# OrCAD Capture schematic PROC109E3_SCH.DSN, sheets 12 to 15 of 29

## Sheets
12 12. SOC2: size C; title: SOC2
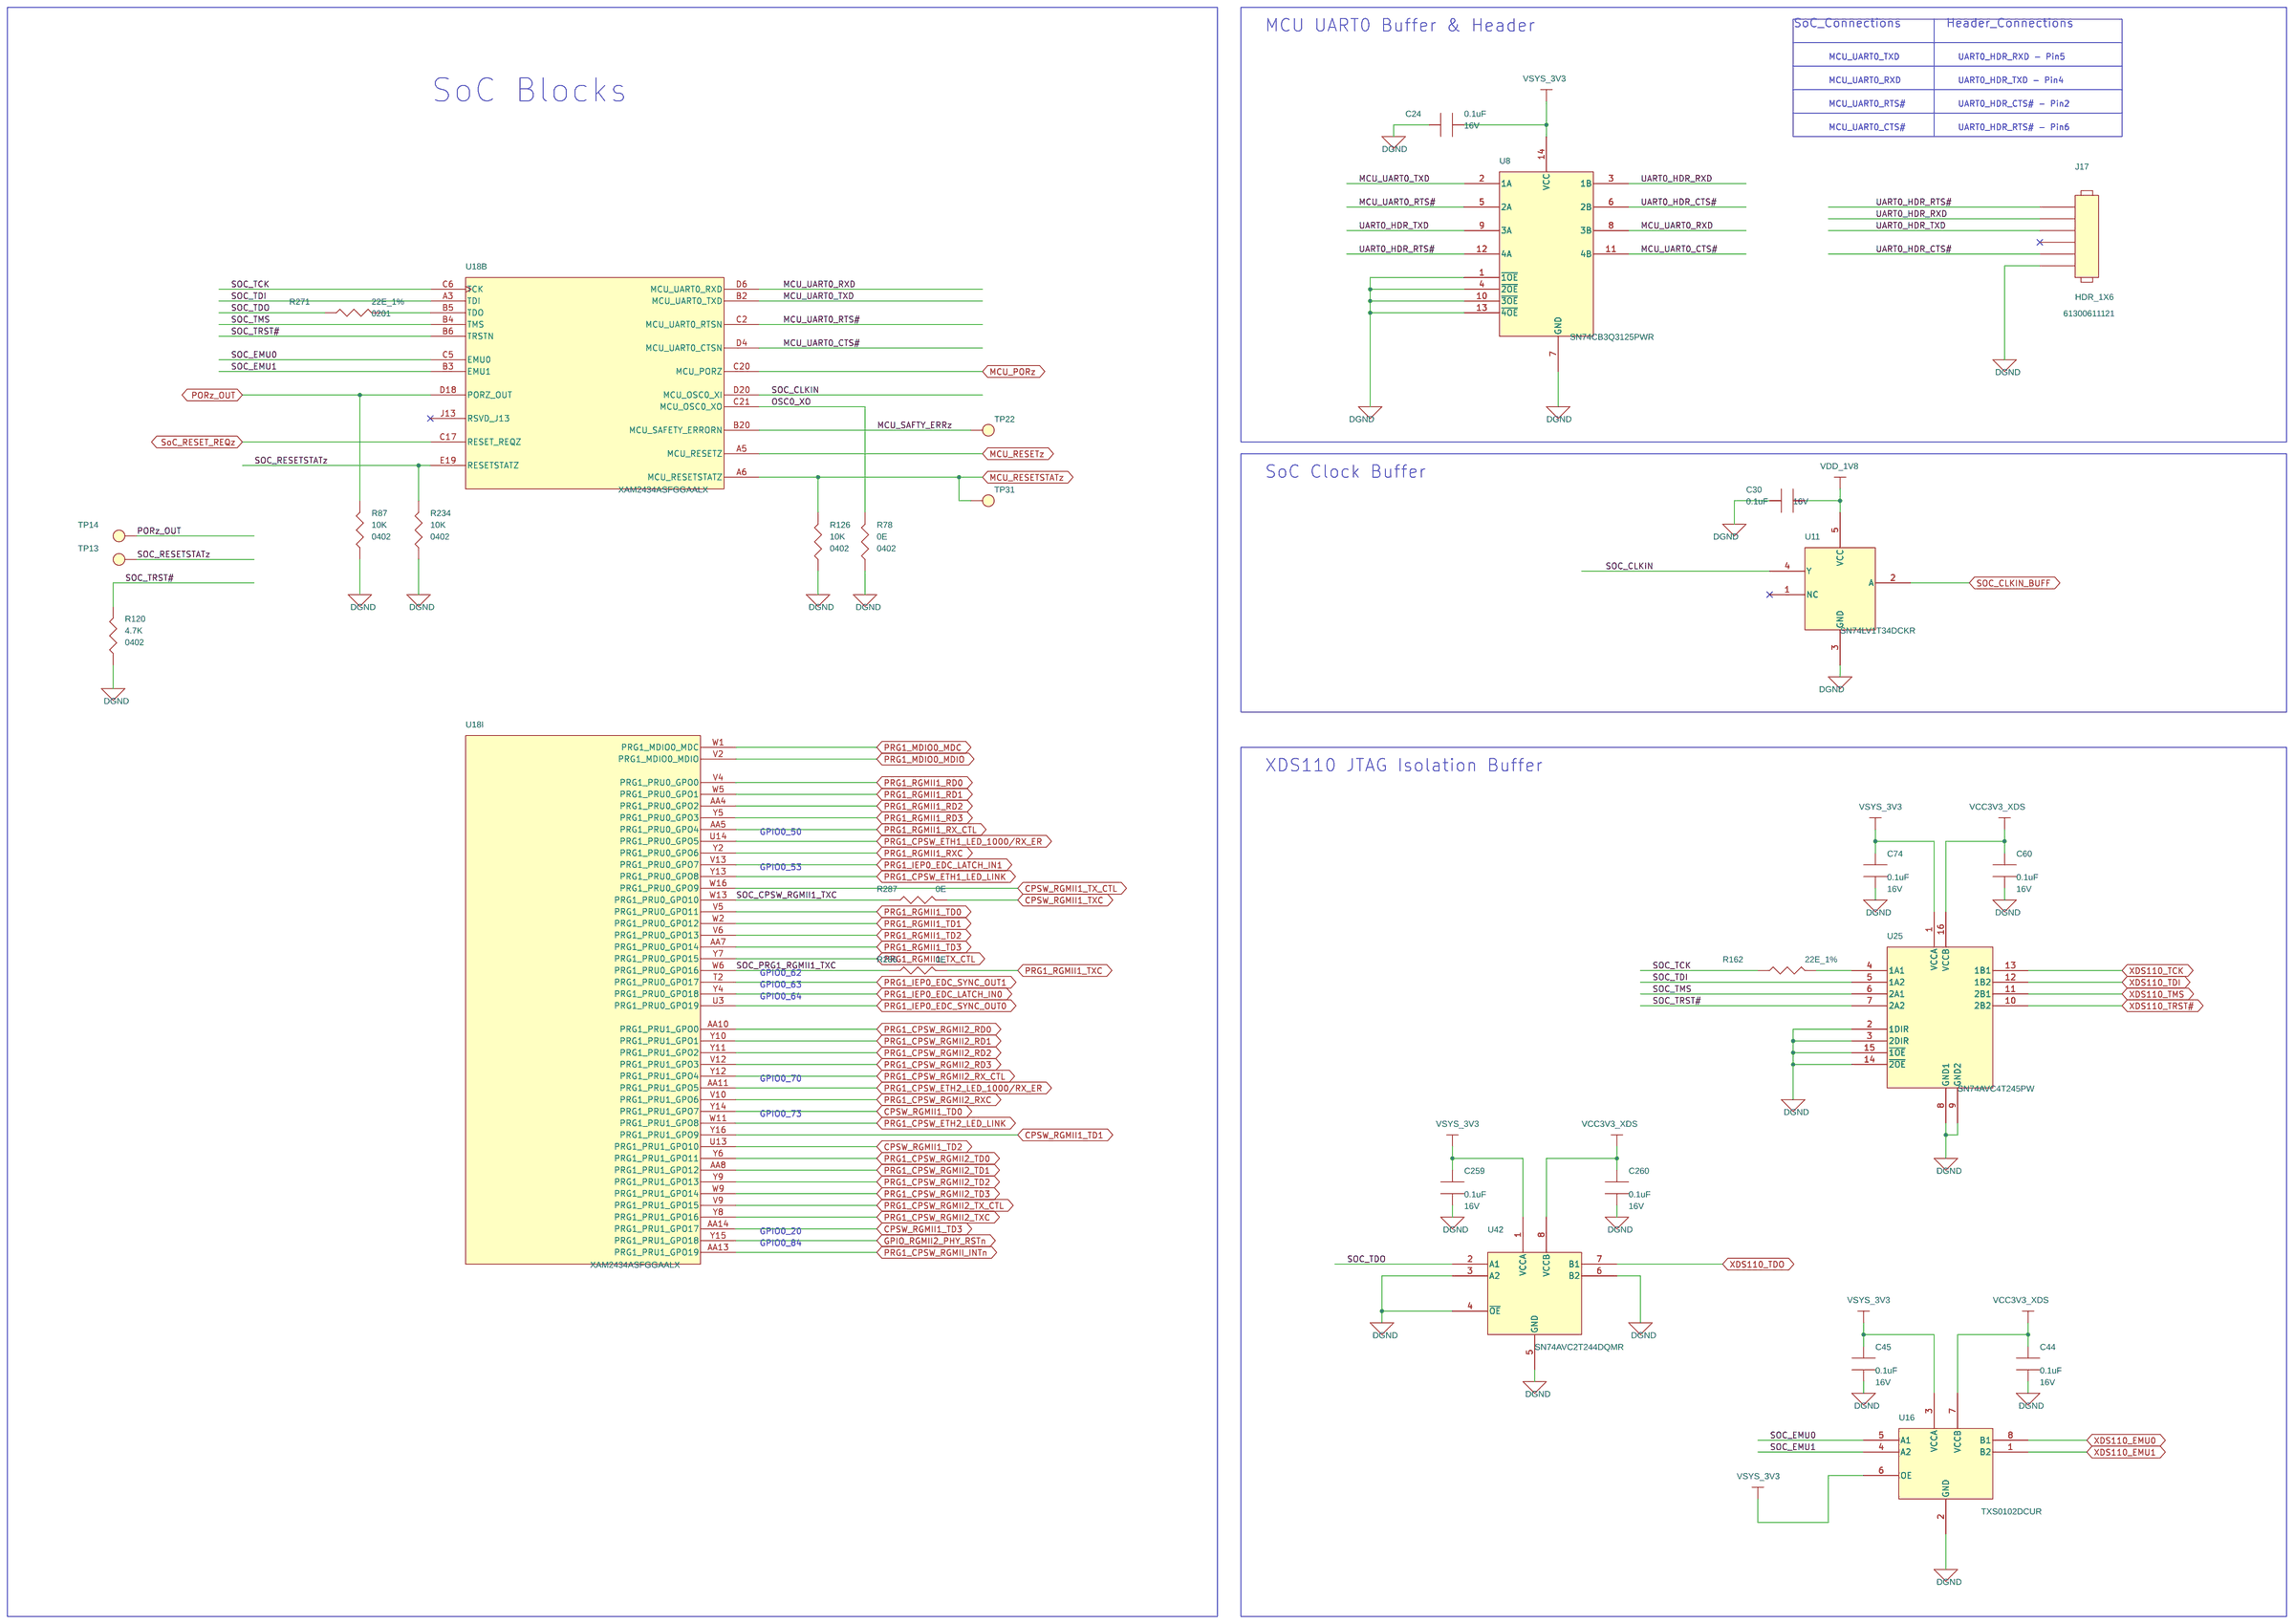
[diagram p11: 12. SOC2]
13 13. MCAN_eQEP_FSI_MUX_USR_LEDs: size C; title: MCAN_eQEP_FSI_MUX
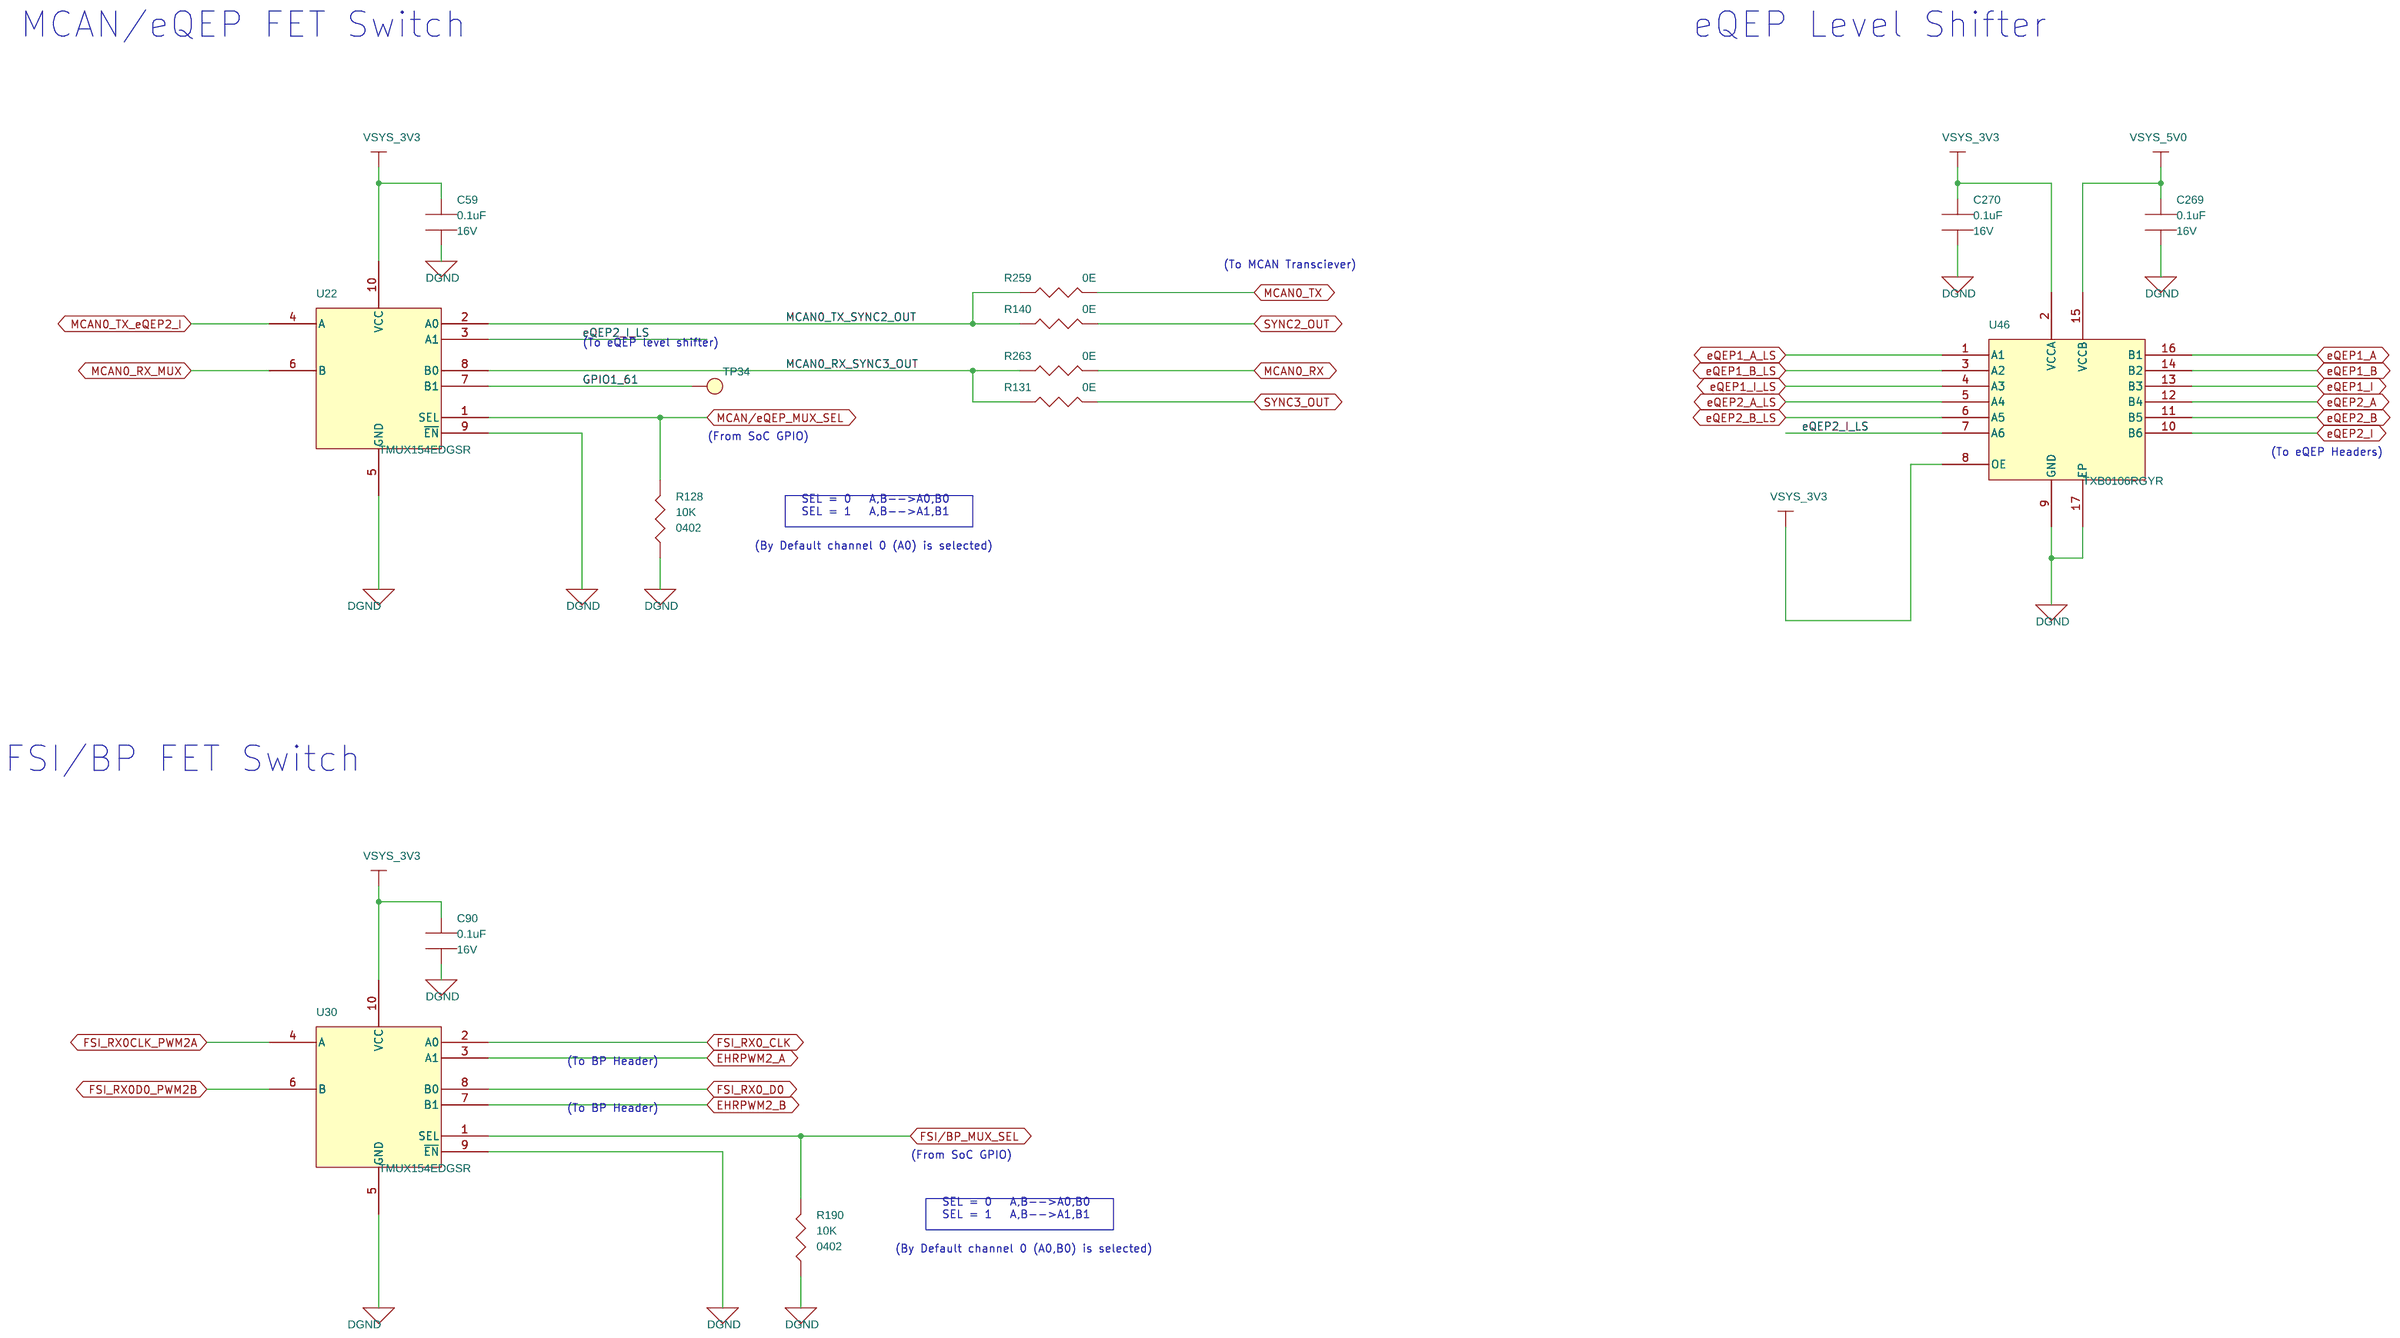
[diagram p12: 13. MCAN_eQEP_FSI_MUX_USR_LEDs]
14 14. CAN_eQEP_FSI_HDR_CLK_BUFFER: size C; title: CAN_eQEP_FSI_HEADERs & CLOCK BUFFER
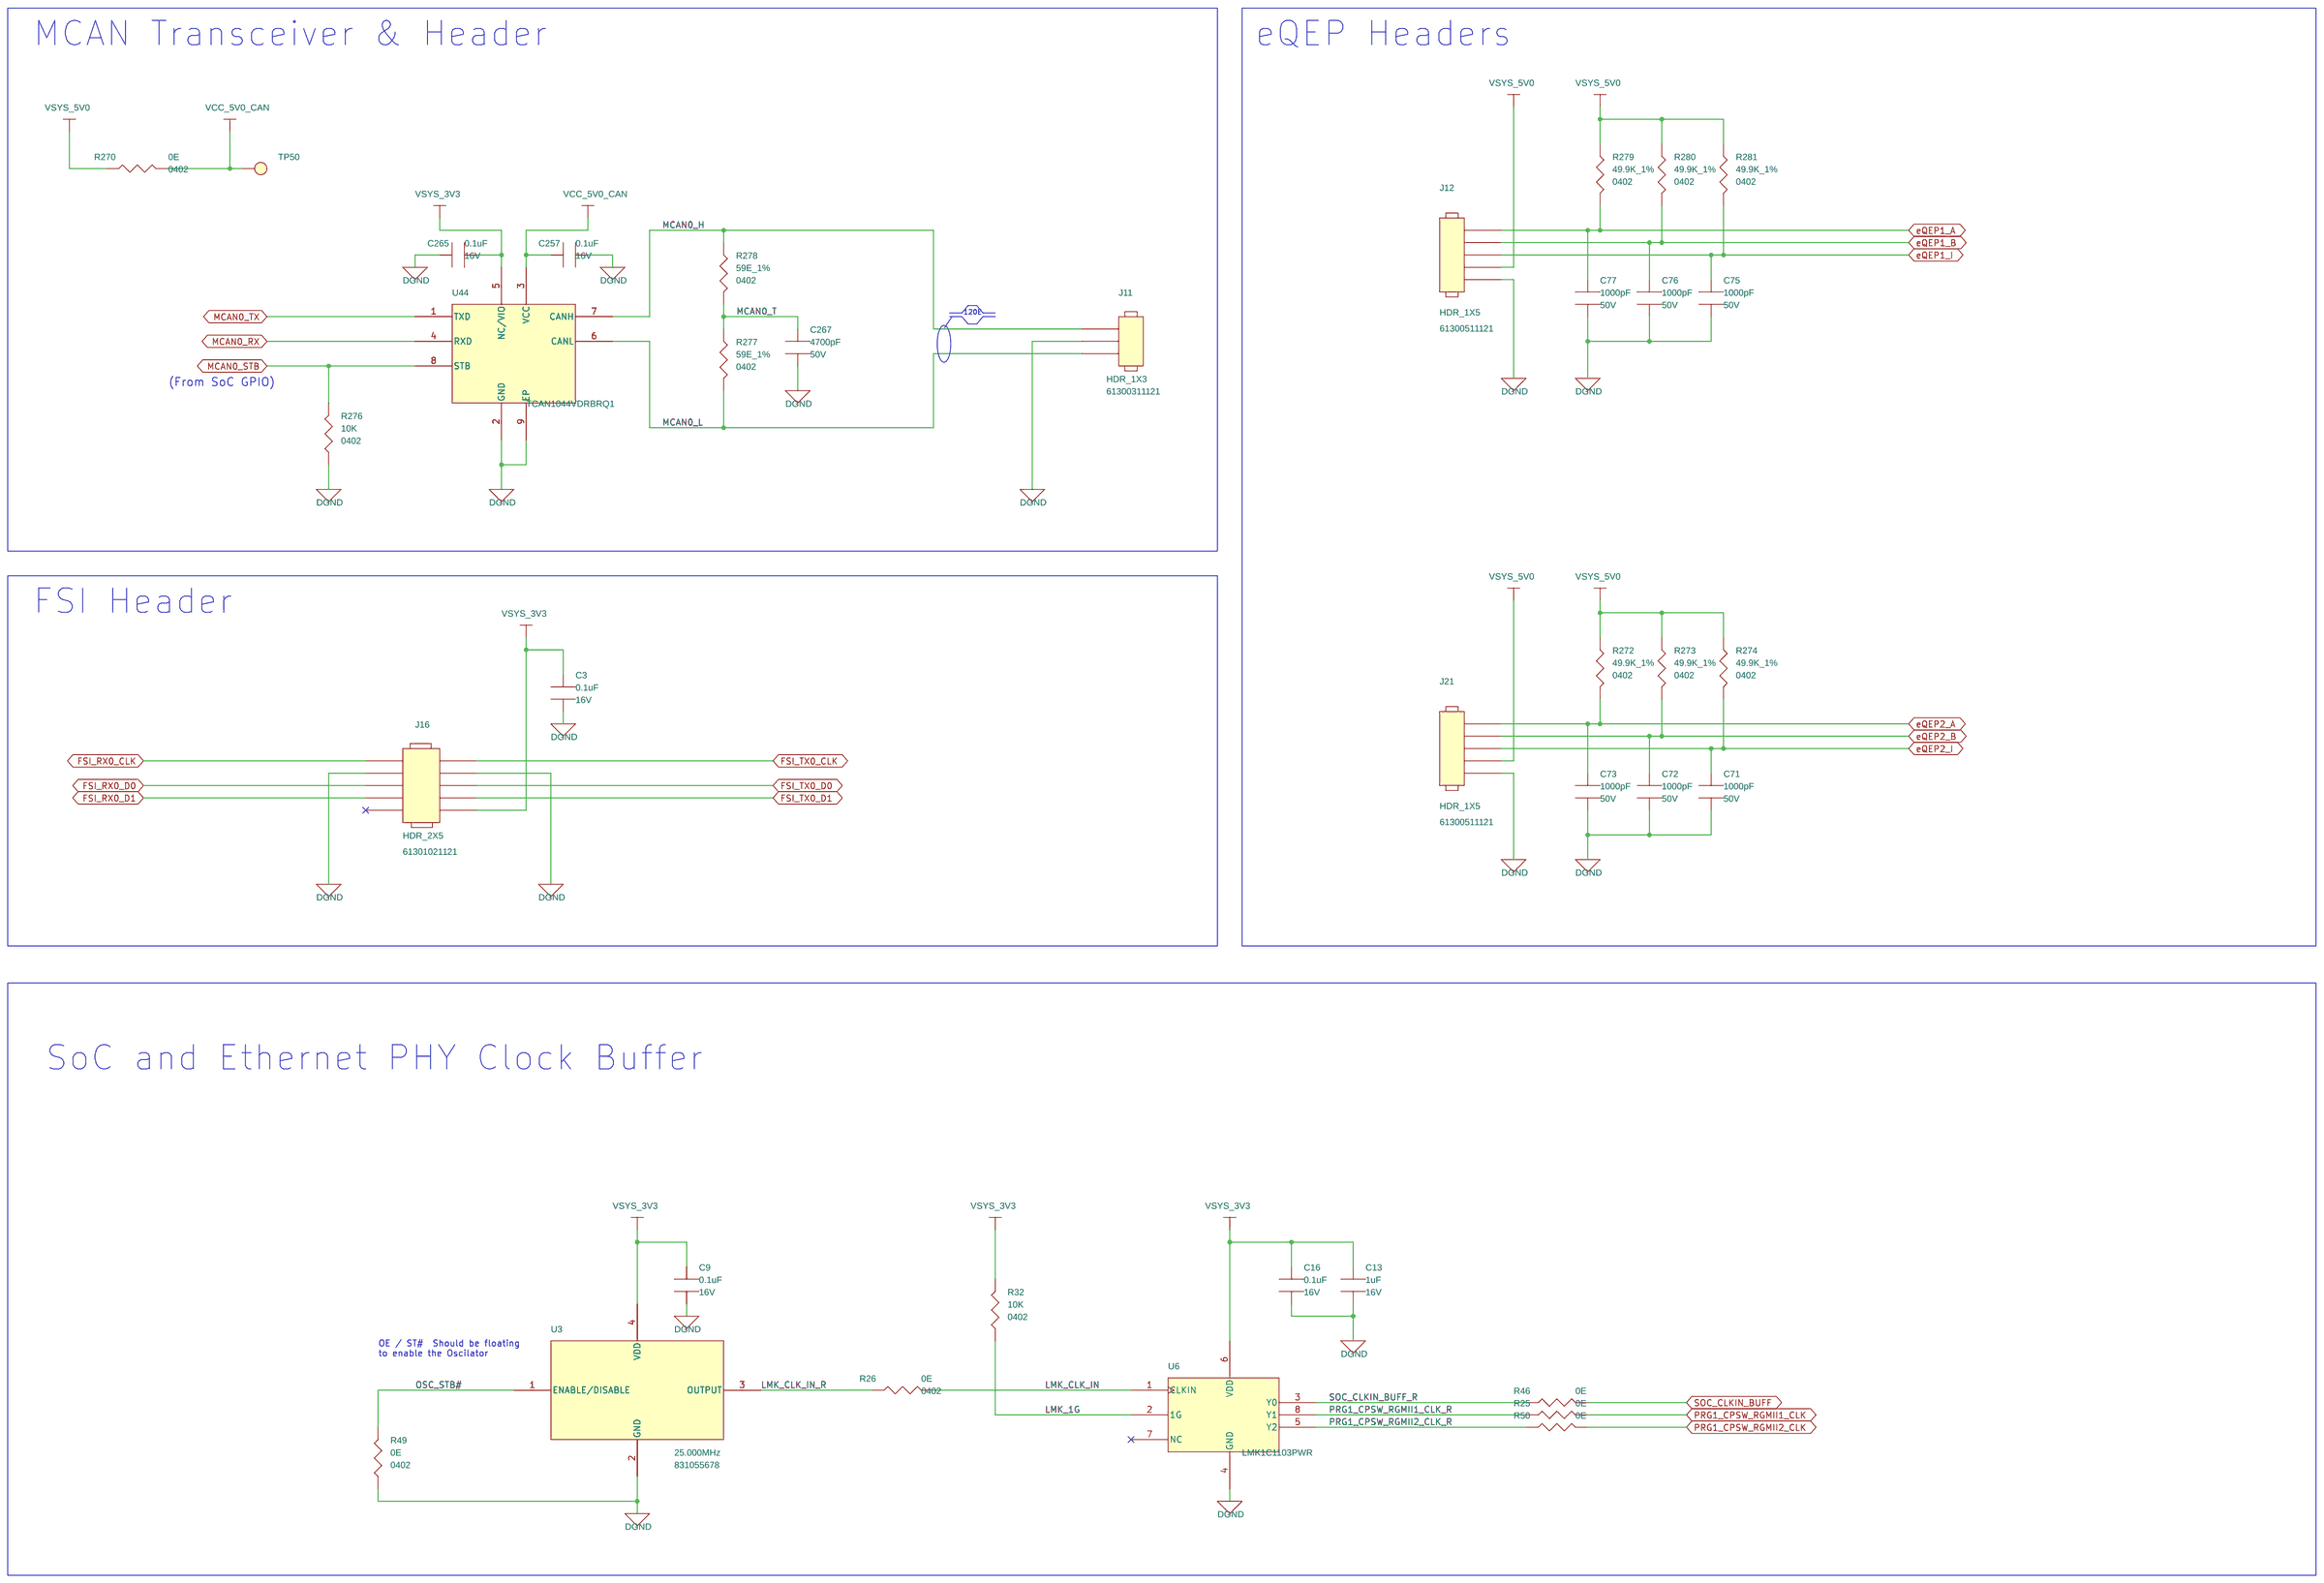
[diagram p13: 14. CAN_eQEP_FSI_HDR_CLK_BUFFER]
15 15. SOC_QSPI_BOARD_ID_EEPROM: size C; title: QSPI_BOARD_ID_EEPROM
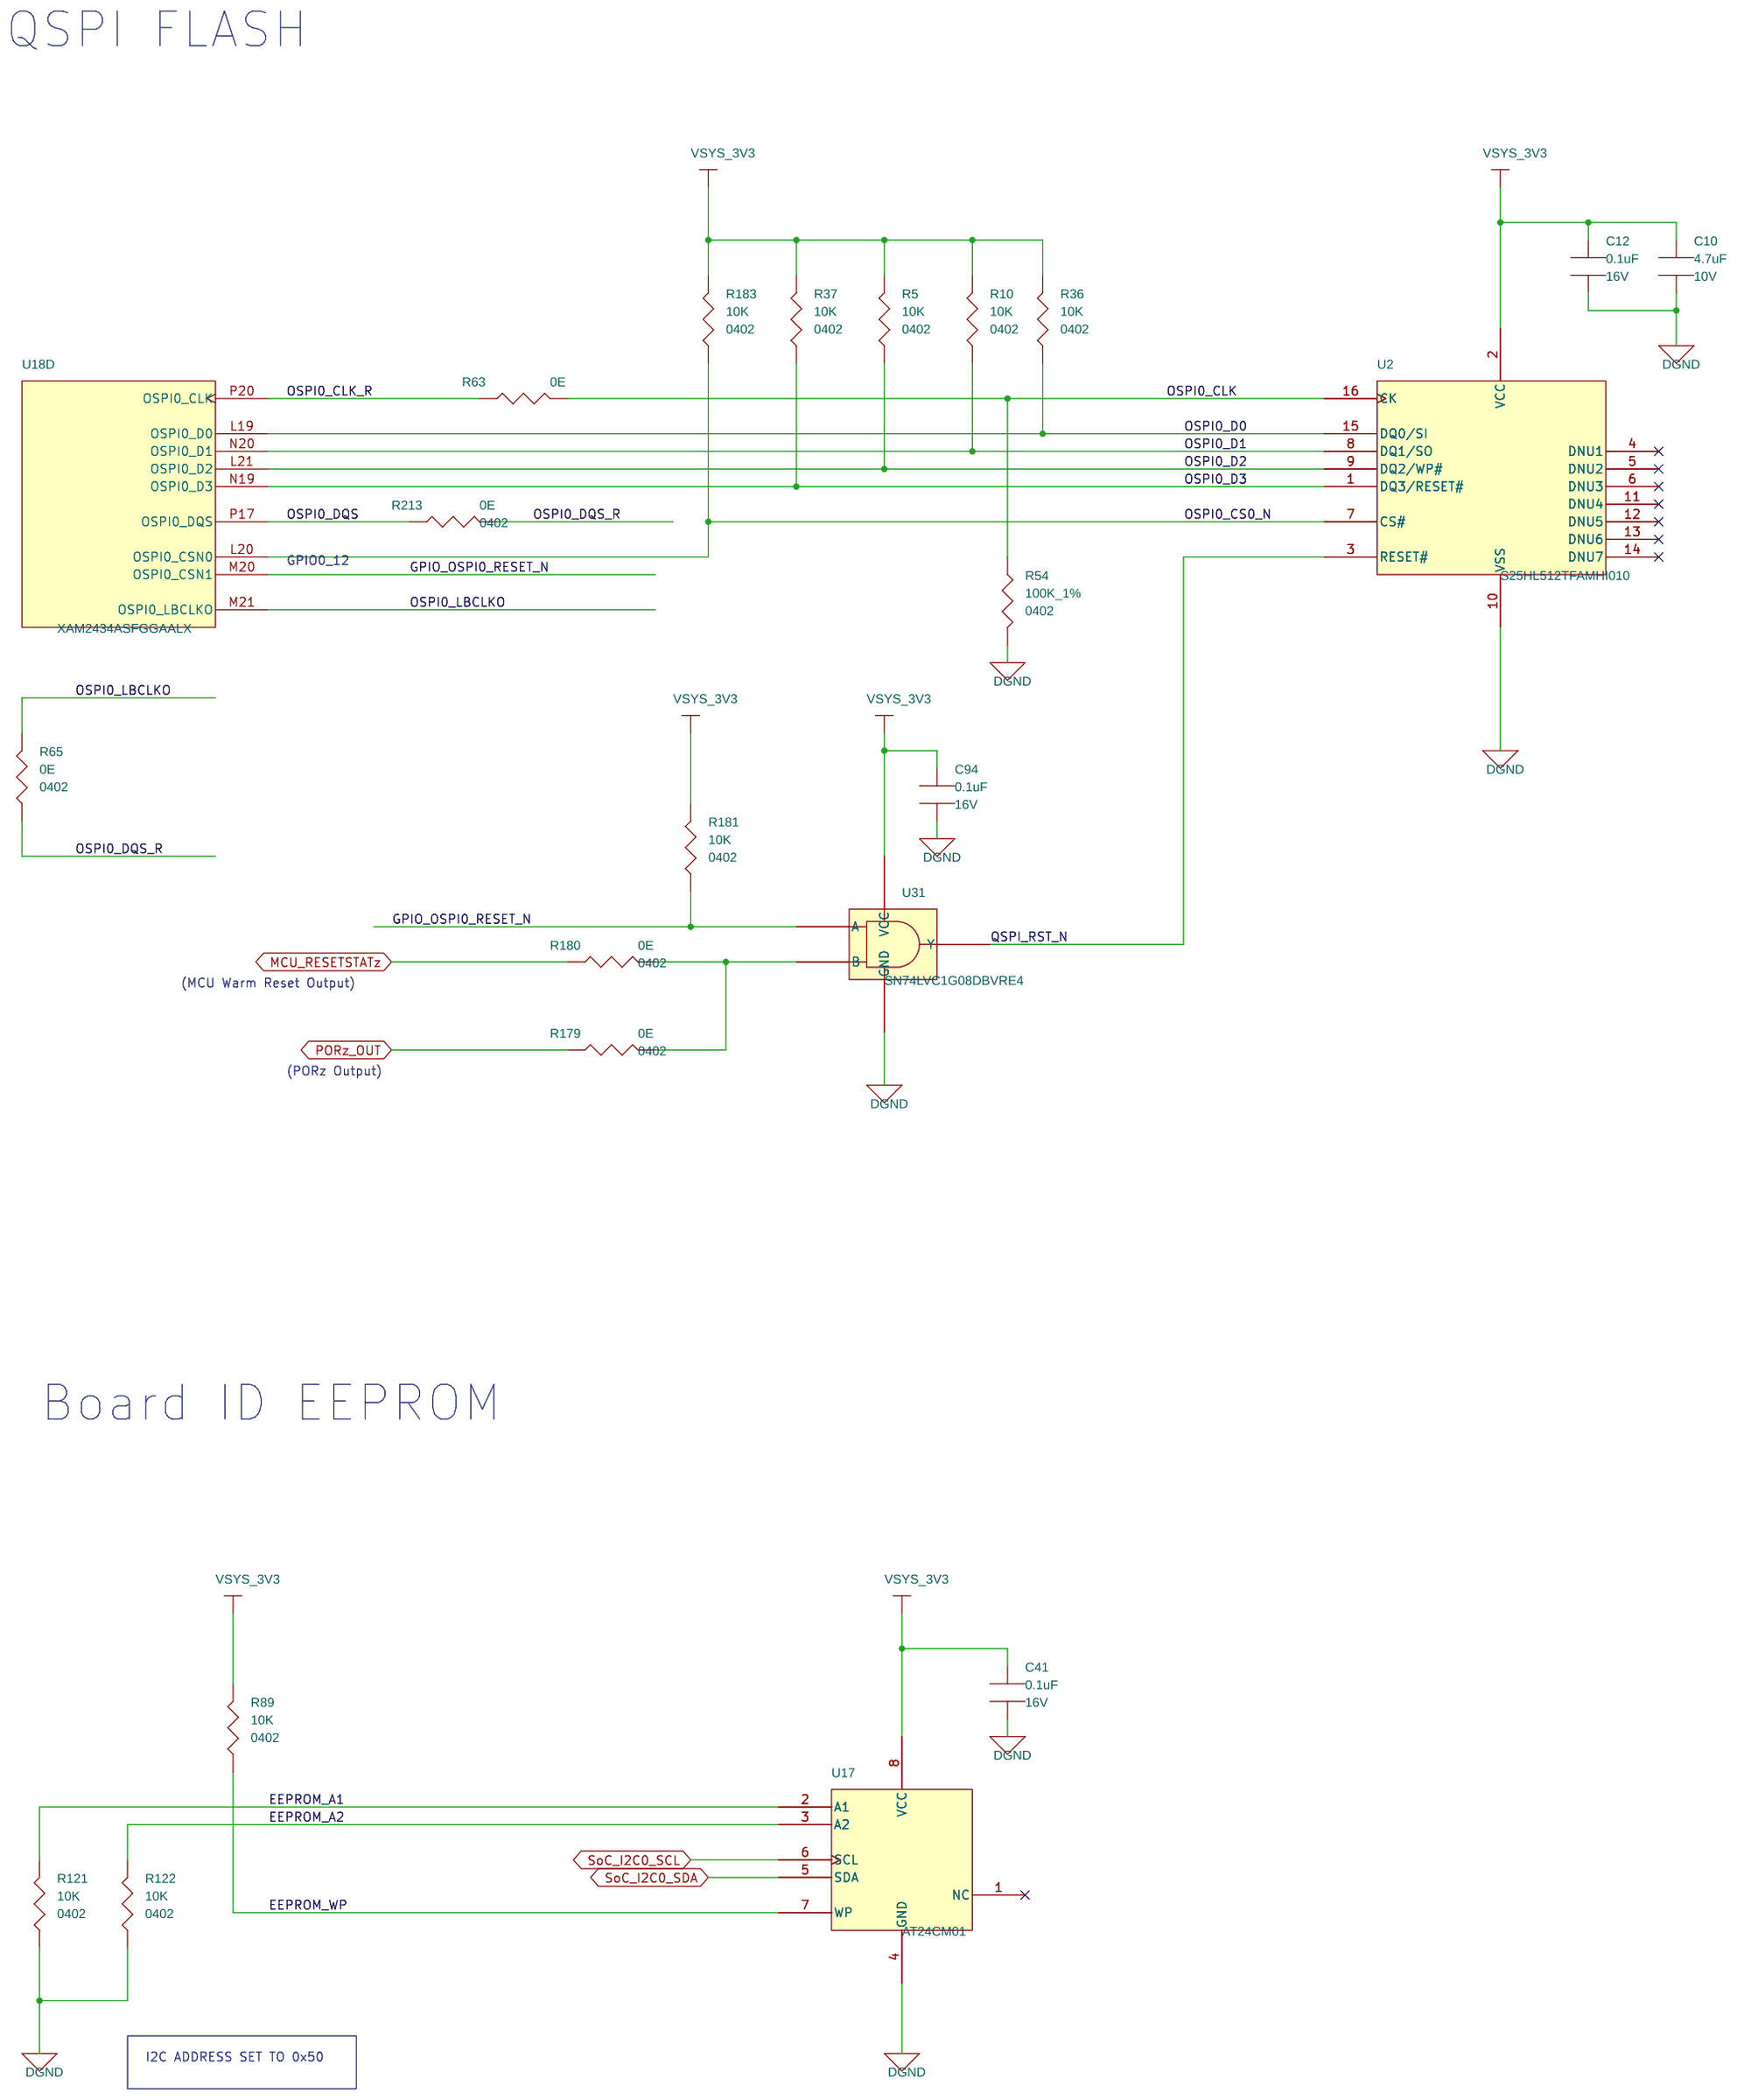
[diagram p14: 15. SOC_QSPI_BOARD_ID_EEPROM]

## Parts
sheet 12. SOC2
C24  0.1uF  [CAP0201_0-5]
C30  0.1uF  [CAP0201_0-5]
C44  0.1uF  [CAP0201_0-5]
C45  0.1uF  [CAP0201_0-5]
C60  0.1uF  [CAP0201_0-5]
C74  0.1uF  [CAP0201_0-5]
C259  0.1uF  [CAP0201_0-5]
C260  0.1uF  [CAP0201_0-5]
J17  HDR_1X6  [HDR_1X6_61300611121_S_T_8-6]
R78  0E  [RES0402_0-5]
R87  10K  [RES0402_0-5]
R120  4.7K  [RES0402_0-5]
R126  10K  [RES0402_0-5]
R162  22E_1%  [RES0201_0-5]
R234  10K  [RES0402_0-5]
R271  22E_1%  [RES0201_0-5]
R286  0E  [RES0402_0-5]
R287  0E  [RES0402_0-5]
TP13  TP20_SMD  [TP20_SMD]
TP14  TP20_SMD  [TP20_SMD]
TP22  TP20_SMD  [TP20_SMD]
TP31  TP20_SMD  [TP20_SMD]
U8  SN74CB3Q3125PWR  [TSSOP14_25-59_205X180_1-2]
U11  SN74LV1T34DCKR  [SC70-5_1-1]
U16  TXS0102DCUR  [VSSOP8_19-68_85X95_0-9]
U25  SN74AVC4T245PW  [TSSOP16_25-59_205X180]
U42  SN74AVC2T244DQMR  [X2SON8_15-74_70X50]
sheet 13. MCAN_eQEP_FSI_MUX_USR_LEDs
C59  0.1uF  [CAP0201_0-5]
C90  0.1uF  [CAP0201_0-5]
C269  0.1uF  [CAP0201_0-5]
C270  0.1uF  [CAP0201_0-5]
R128  10K  [RES0402_0-5]
R131  0E  [RES0402_0-5]
R140  0E  [RES0402_0-5]
R190  10K  [RES0402_0-5]
R259  0E  [RES0402_0-5]
R263  0E  [RES0402_0-5]
TP34  TP20_SMD  [TP20_SMD]
U22  TMUX154EDGSR  [MSOP10_19-68_120X120_1-1]
U30  TMUX154EDGSR  [MSOP10_19-68_120X120_1-1]
U46  TXB0106RGYR  [QFN16_19-68_160X140_1]
sheet 14. CAN_eQEP_FSI_HDR_CLK_BUFFER
C3  0.1uF  [CAP0201_0-5]
C9  0.1uF  [CAP0201_0-5]
C13  1uF  [CAP0201_0-5]
C16  0.1uF  [CAP0201_0-5]
C71  1000pF  [CAP0402_0-75]
C72  1000pF  [CAP0402_0-75]
C73  1000pF  [CAP0402_0-75]
C75  1000pF  [CAP0402_0-75]
C76  1000pF  [CAP0402_0-75]
C77  1000pF  [CAP0402_0-75]
C257  0.1uF  [CAP0201_0-5]
C265  0.1uF  [CAP0201_0-5]
C267  4700pF  [CAP0402_0-75]
J11  HDR_1X3  [HDR_1X3_100_S_T]
J12  HDR_1X5  [HDR_1X5_61300511121_S_T_8-6]
J16  HDR_2X5  [HDR_2X5_61301021121_S_T_8-6]
J21  HDR_1X5  [HDR_1X5_61300511121_S_T_8-6]
R25  0E  [RES0402_0-5]
R26  0E  [RES0402_0-5]
R32  10K  [RES0402_0-5]
R46  0E  [RES0402_0-5]
R49  0E  [RES0402_0-5]
R50  0E  [RES0402_0-5]
R270  0E  [RES0402_0-5]
R272  49.9K_1%  [RES0402_0-5]
R273  49.9K_1%  [RES0402_0-5]
R274  49.9K_1%  [RES0402_0-5]
R276  10K  [RES0402_0-5]
R277  59E_1%  [RES0402_0-5]
R278  59E_1%  [RES0402_0-5]
R279  49.9K_1%  [RES0402_0-5]
R280  49.9K_1%  [RES0402_0-5]
R281  49.9K_1%  [RES0402_0-5]
TP50  TP20_SMD  [TP20_SMD]
U3  25.000MHz  [OSC4_ASEK_130X100_SMD_1-2]
U6  LMK1C1103PWR  [TSSOP8_25-59_125X180_1-2]
U44  TCAN1044VDRBRQ1  [SON8_25-59_130X130_1]
sheet 15. SOC_QSPI_BOARD_ID_EEPROM
C10  4.7uF  [CAP0402_0-75]
C12  0.1uF  [CAP0201_0-5]
C41  0.1uF  [CAP0201_0-5]
C94  0.1uF  [CAP0201_0-5]
R5  10K  [RES0402_0-5]
R10  10K  [RES0402_0-5]
R36  10K  [RES0402_0-5]
R37  10K  [RES0402_0-5]
R54  100K_1%  [RES0402_0-5]
R63  0E  [RES0402_0-5]
R65  0E  [RES0402_0-5]
R89  10K  [RES0402_0-5]
R121  10K  [RES0402_0-5]
R122  10K  [RES0402_0-5]
R179  0E  [RES0402_0-5]
R180  0E  [RES0402_0-5]
R181  10K  [RES0402_0-5]
R183  10K  [RES0402_0-5]
R213  0E  [RES0402_0-5]
U2  S25HL512TFAMHI010  [SOIC16_W_2-7]
U17  AT24CM01  [TSSOP8_25-59_125X180_1-2]
U31  SN74LVC1G08DBVRE4  [SOT23-5]
sheet 25. SOC_ANALOG_POWER_DECAPs
U18  XAM2434ASFGGAALX  [BGA293_19-68_440X440_1]  (sections A,B,C,D,E,F,G,H,I,J,K,L,M)

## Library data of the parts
C3 C9 C12 C16 C24 C30 C41 C44 C45 C60 C74 C94 C257 C259 C260 C265 = CAP: CAP CERAMIC 0.1uF 16V 10% X5R 0201; Chkd/date: MANIRAJA/230118; Crtd /date: MANIRAJA/230118; Custom_Duty: 15%; Customs_HS_Code: 85322990; Distributor_name: DIGIKEY; Distributor_part_number: 490-14305-1-ND; Footprint Path: Y:\MIS_DATABASE\Library\ALTIUM_TOOL\PCB_FOOTPRINTS\Altium_Footprint_Lib.PcbLib; Height: 0.33MM; Library Path: Y:\MIS_DATABASE\Library\ALTIUM_TOOL\SCHEMATICS_PARTS\MS_DISCRETE_Library.schlib; Mfr_name: MURATA; Mfr_part_number: GRM033R61C104KE14D; Mistral Part No: 120009030072-R; Package: 0201; Part_type: CAPACITORS\CERAMIC; Project: TI_MAXIE_CPB; RoHS: RoHS; Temperature: -55°C+85°C; Tolerance: 10%; Voltage: 16V; Wattage: NA; Weight: 0.33mg; Datasheet: Y:\MIS_DATABASE\DATASHEETS\CAPACITORS\GRM033R61C104KE14.PDF
J17 = HEADER_6X1: CON HDR 1X6 2.54MM PITCH ST TH; Chkd/date: MANIRAJA/161219; Crtd /date: MANIRAJA/161219; Custom_Duty: 24%; Customs_HS_Code: 85369090; Distributor_name: DIGIKEY; Distributor_part_number: 732-5319-ND; Footprint Path: Y:\MIS_DATABASE\Library\ALTIUM_TOOL\PCB_FOOTPRINTS\Altium_Footprint_Lib.PcbLib; Height: 8.54MM; Library Path: Y:\MIS_DATABASE\Library\ALTIUM_TOOL\SCHEMATICS_PARTS\MS_CONNECTOR_Library.schlib; Mfr_name: WURTH ELECTRONICS; Mfr_part_number: 61300611121; Mistral Part No: 150019120017-R; Package: THRU-HOLE; Part_type: CONNECTOR\HEADERS; Project: SD820_NANOSOM_TESTJIG; RoHS: RoHS; Temperature: -40°C+105°C; Tolerance: NA; Voltage: NA; Wattage: NA; Weight: 342.4mg; Datasheet: Y:\MIS_DATABASE\DATASHEETS\CONNECTORS\6130XXX.PDF
R25 R26 R46 R49 R50 R65 R78 R131 R140 R179 R180 R213 R259 R263 R270 = RESISTOR: RES 0E 1/16W 5% 0402; Chkd/date: VASANTHA/291216; Crtd /date: CHAITHANYA/300911; Custom_Duty: 15%; Customs_HS_Code: 85332119; Distributor_name: DIGIKEY; Distributor_part_number: 311-0.0JRCT-ND; Footprint Path: Y:\MIS_DATABASE\Library\ALTIUM_TOOL\PCB_FOOTPRINTS\Altium_Footprint_Lib.PcbLib; Height: 0.40MM; Library Path: Y:\MIS_DATABASE\Library\ALTIUM_TOOL\SCHEMATICS_PARTS\MS_DISCRETE_Library.schlib; Mfr_name: YAGEO AMERICA; Mfr_part_number: RC0402JR-070RL; Mistral Part No: 110011090036-R; Package: 0402; Part_type: RESISTORS\FIXED; Project: VP-4000-PROCESSOR; RoHS: RoHS; Temperature: -55°C+155°C; Tolerance: 5%; Voltage: NA; Wattage: 1/16W; Weight: 0.65mg; Datasheet: Y:\MIS_DATABASE\DATASHEETS\RESISTORS\RCXXXXL-SER_MAR18.PDF
R5 R10 R32 R36 R37 R87 R89 R121 R122 R126 R128 R181 R183 R190 R234 R276 = RESISTOR: RES 10K 1/16W 5% 0402; Chkd/date: VASANTHA/061216; Crtd /date: MAZHAR/230805; Custom_Duty: 15%; Customs_HS_Code: 85332119; Distributor_name: DIGIKEY; Distributor_part_number: 311-10KJRCT-ND; Footprint Path: Y:\MIS_DATABASE\Library\ALTIUM_TOOL\PCB_FOOTPRINTS\Altium_Footprint_Lib.PcbLib; Height: 0.40MM; Library Path: Y:\MIS_DATABASE\Library\ALTIUM_TOOL\SCHEMATICS_PARTS\MS_DISCRETE_Library.schlib; Mfr_name: YAGEO AMERICA; Mfr_part_number: RC0402JR-0710KL; Mistral Part No: 110011060021-R; Package: 0402; Part_type: RESISTORS\FIXED; Project: HSE; RoHS: RoHS; Temperature: -55°C+155°C; Tolerance: 5%; Voltage: NA; Wattage: 1/16W; Weight: 0.65mg; Datasheet: Y:\MIS_DATABASE\DATASHEETS\RESISTORS\RCXXXXL-SER_MAR18.PDF
R120 = RESISTOR: RES 4.7K 1/16W 5% 0402; Chkd/date: VASANTHA/130516; Crtd /date: VASANTHA/130516; Custom_Duty: 15%; Customs_HS_Code: 85332119; Distributor_name: DIGIKEY; Distributor_part_number: 311-4.7KJRCT-ND; Footprint Path: Y:\MIS_DATABASE\Library\ALTIUM_TOOL\PCB_FOOTPRINTS\Altium_Footprint_Lib.PcbLib; Height: 0.40MM; Library Path: Y:\MIS_DATABASE\Library\ALTIUM_TOOL\SCHEMATICS_PARTS\MS_DISCRETE_Library.schlib; Mfr_name: YAGEO AMERICA; Mfr_part_number: RC0402JR-074K7L; Mistral Part No: 110011060001-R; Package: 0402; Part_type: RESISTORS\FIXED; Project: TMDXCSK368; RoHS: RoHS; Temperature: -55°C+155°C; Tolerance: 5%; Voltage: NA; Wattage: 1/16W; Weight: 0.65mg; Datasheet: Y:\MIS_DATABASE\DATASHEETS\RESISTORS\RCXXXXL-SER_MAR18.PDF
R162 R271 = RESISTOR: RES 22E 1/20W 1% 0201; Chkd/date: MANIRAJA/080319; Crtd /date: ALVY/080319; Custom_Duty: 15%; Customs_HS_Code: 85332119; Distributor_name: DIGIKEY; Distributor_part_number: YAG2518CT-ND; Footprint Path: Y:\MIS_DATABASE\Library\ALTIUM_TOOL\PCB_FOOTPRINTS\Altium_Footprint_Lib.PcbLib; Height: 0.26MM; Library Path: Y:\MIS_DATABASE\Library\ALTIUM_TOOL\SCHEMATICS_PARTS\MS_DISCRETE_Library.schlib; Mfr_name: YAGEO AMERICA; Mfr_part_number: RC0201FR-0722RL; Mistral Part No: 110009030522-R; Package: 0201; Part_type: RESISTORS\FIXED; Project: AM654x_SOM; RoHS: RoHS; Temperature: -55°C+125°C; Tolerance: 1%; Voltage: NA; Wattage: 1/20W; Weight: 0.17mg; Datasheet: Y:\MIS_DATABASE\DATASHEETS\RESISTORS\RCXXXXL-SER_MAR18.PDF
R63 R286 R287 = RESISTOR: RES 0E 1/16W 5% 0402; Chkd/date: VASANTHA/291216; Crtd /date: CHAITHANYA/300911; Custom_Duty: 15%; Customs_HS_Code: 85332119; Distributor_name: DIGIKEY; Distributor_part_number: 311-0.0JRCT-ND; Footprint Path: Y:\MIS_DATABASE\Library\ALTIUM_TOOL\PCB_FOOTPRINTS\Altium_Footprint_Lib.PcbLib; Height: 0.40MM; Library Path: Y:\MIS_DATABASE\Library\ALTIUM_TOOL\SCHEMATICS_PARTS\MS_DISCRETE_Library.schlib; Mfr_name: YAGEO AMERICA; Mfr_part_number: RC0402JR-070RL; Mistral Part No: 110011090036-R; Package: 0402; Part_type: RESISTORS\FIXED; Project: VP-4000-PROCESSOR; RoHS: RoHS; SIGNAL_MODEL: RESISTOR_RES0402_0-5_0E_0E; Temperature: -55°C+155°C; Tolerance: 5%; Voltage: NA; Wattage: 1/16W; Weight: 0.65mg; Datasheet: Y:\MIS_DATABASE\DATASHEETS\RESISTORS\RCXXXXL-SER_MAR18.PDF
TP13 TP14 TP22 TP31 TP34 TP50 = TESTPOINT: TESTPOINT CIR 20 SMD; Chkd/date: SHREESHAIL/171006; Crtd /date: MAZHAR/171006; Custom_Duty: NA; Customs_HS_Code: NA; Distributor_name: NA; Distributor_part_number: NA; Footprint Path: Y:\MIS_DATABASE\Library\ALTIUM_TOOL\PCB_FOOTPRINTS\Altium_Footprint_Lib.PcbLib; Height: NA; Library Path: Y:\MIS_DATABASE\Library\ALTIUM_TOOL\SCHEMATICS_PARTS\MS_DISCRETE_Library.schlib; MECHANICAL 3D STEP FILE: NA; Mfr_name: LOCAL; Mistral Part No: NA; Package: SMD; Project: BT MODULE_CSRBC04; RoHS: NA; Temperature: NA; Tolerance: NA; Voltage: NA; Wattage: NA; Weight: NA; Datasheet: NA
U8 = SN74CBTLV3125PWR_TSSOP14: IC 2.5/3.3V QUADRUPLE HIGH-BANDWIDTH FET BUS SWITCH TSSOP14; Chkd/date: MANIRAJA/241018; Crtd /date: ALVY/241018; Custom_Duty: 15%; Customs_HS_Code: 85423100; Distributor_name: DIGIKEY; Distributor_part_number: 296-16804-1-ND; Footprint Path: Y:\MIS_DATABASE\Library\ALTIUM_TOOL\PCB_FOOTPRINTS\Altium_Footprint_Lib.PcbLib; Height: 1.20MM; Library Path: Y:\MIS_DATABASE\Library\ALTIUM_TOOL\SCHEMATICS_PARTS\MS_COMBINATIONAL_Library.schlib; Mfr_name: TEXAS INSTRUMENTS; Mistral Part No: 141018100021-R; Package: TSSOP14; Part_type: ICS\DIGITAL\COMBINATIONAL; Project: TI_J7ES_EVM_CP; RoHS: RoHS; Temperature: -40°C+85°C; Tolerance: NA; Voltage: NA; Wattage: NA; Weight: 57.2mg; Datasheet: Y:\MIS_DATABASE\DATASHEETS\ICS\DIGITAL\COMBINATIONAL\SN74CB3Q3125.PDF
U11 = SN74LVC1G07DBVR_SOT23-5: IC SINGLE BUFFER GATE CMOS LOGIC LEVEL SHIFTER SC70-5; Chkd/date: MANIRAJA/130819; Crtd /date: MANIRAJA/130819; Custom_Duty: 15%; Customs_HS_Code: 85423100; Distributor_name: DIGIKEY; Distributor_part_number: 296-37177-1-ND; Footprint Path: Y:\MIS_DATABASE\Library\ALTIUM_TOOL\PCB_FOOTPRINTS\Altium_Footprint_Lib.PcbLib; Height: 1.10MM; Library Path: Y:\MIS_DATABASE\Library\ALTIUM_TOOL\SCHEMATICS_PARTS\MS_GATE_Library.schlib; Mfr_name: TEXAS INSTRUMENTS; Mistral Part No: 141019080005-R; Package: SC70-5; Part_type: ICS\DIGITAL\GATES; Project: BRUKER_SD820_COMMONDO; RoHS: RoHS; Temperature: -40°C+125°C; Tolerance: NA; Voltage: NA; Wattage: NA; Weight: 20mg; Datasheet: Y:\MIS_DATABASE\DATASHEETS\ICS\DIGITAL\GATES\SN74LV1T34.PDF
U16 = TXS0102DCUR_VSSOP8: IC 2BIT BI-DIR VOLTAGE-LEVEL TRANSLATOR US8(VSSOP8); Chkd/date: MANIRAJA/130617; Crtd /date: SHREESHAIL/190108; Custom_Duty: 15%; Customs_HS_Code: 85423100; Distributor_name: DIGIKEY; Distributor_part_number: 296-21931-1-ND; Footprint Path: Y:\MIS_DATABASE\Library\ALTIUM_TOOL\PCB_FOOTPRINTS\Altium_Footprint_Lib.PcbLib; Height: 0.90MM; Library Path: Y:\MIS_DATABASE\Library\ALTIUM_TOOL\SCHEMATICS_PARTS\MS_MISCINTERFACE_Library.schlib; Mfr_name: TEXAS INSTRUMENTS; Mistral Part No: 141009030376-R; Package: US8; Part_type: ICS\INTERFACE\LEVEL TRANSLATOR; Project: SD_WATERLOO; RoHS: RoHS; Temperature: -40°C+85°C; Tolerance: NA; Voltage: NA; Wattage: NA; Weight: 9.6mg; Datasheet: Y:\MIS_DATABASE\DATASHEETS\ICS\INTERFACE\TXS0102.PDF
U25 = SN74AVC4T245PW_TSSOP16: IC 4-BIT DUAL SUPPLY BUS TRANSCEIVER TSSOP16; Chkd/date: SHREESHAIL/030506; Crtd /date: MAZHAR/270406; Custom_Duty: 15%; Customs_HS_Code: 85423100; Distributor_name: MOUSER; Distributor_part_number: 595-SN74AVC4T245PW; Height: 1.20MM; Mfr_name: TEXAS INSTRUMENTS; Mistral Part No: 141009030111-R; Package: TSSOP16; Part_type: ICS\DIGITAL\COMBINATIONAL; Project: VOCERA; RoHS: Sb/ Br FREE; Datasheet: Y:\MIS_DATABASE\DATASHEETS\ICS\DIGITAL\BUSTRANSCEIVER\SN74AVC4T245.PDF
U42 = SN74AVC2T244DQMR_X2SON8: IC 2-BIT UNDIRECTIONAL VOLTAGE-LEVEL TRANSLATOR X2SON8; Chkd/date: VASANTHA/060516; Crtd /date: VASANTHA/030316; Customs_HS_Code: 15%; Distributor_name: DIGIKEY; Distributor_part_number: 296-29674-1-ND; Height: 0.40MM; Mfr_name: TEXAS INSTRUMENTS; Mistral Part No: 141016030002-R; Package: X2SON8; Part_type: ICS\INTERFACE\LEVEL TRANSLATOR; Pb-Free: 85423100; Project: OCTASIC_3600; RoHS: RoHS; Temperature: -40°C+85°C; Tolerance: NA; Voltage: NA; Wattage: NA; Weight: NA; Datasheet: Y:\MIS_DATABASE\DATASHEETS\ICS\INTERFACE\SN74AVC2T244.PDF
C59 C90 C269 C270 = CAP: CAP CERAMIC 0.1uF 16V 10% X5R 0201; Alt_Mfr_name: YAGEO AMERICA; Alt_Mfr_part_number: CC0402KRX5R8BB104; Chkd/date: MANIRAJA/230118; Crtd /date: MANIRAJA/230118; Custom_Duty: 15%; Customs_HS_Code: 85322990; Distributor_name: DIGIKEY; Distributor_part_number: 490-14305-1-ND; Footprint Path: Y:\MIS_DATABASE\Library\ALTIUM_TOOL\PCB_FOOTPRINTS\Altium_Footprint_Lib.PcbLib; Height: 0.33MM; Library Path: Y:\MIS_DATABASE\Library\ALTIUM_TOOL\SCHEMATICS_PARTS\MS_DISCRETE_Library.schlib; Mfr_name: MURATA; Mfr_part_number: GRM033R61C104KE14D; Mistral Part No: 120009030072-R; Package: 0201; Part_type: CAPACITORS\CERAMIC; Project: TI_MAXIE_CPB; RoHS: RoHS; Temperature: -55°C+85°C; Tolerance: 10%; Voltage: 16V; Wattage: NA; Weight: 0.33mg; Datasheet: Y:\MIS_DATABASE\DATASHEETS\CAPACITORS\GRM033R61C104KE14.PDF
U22 U30 = TMUX154EDGSR_VSSOP10: IC ESD PROTECTED 2-CH 2:1 SWITCH WITH POWERED-OFF PROTECTION VSSOP10; Chkd/date: MANIRAJA/040918; Crtd /date: MANIRAJA/040918; Custom_Duty: 15%; Customs_HS_Code: 85423100; Distributor_name: DIGIKEY; Distributor_part_number: 296-48347-1-ND; Footprint Path: Y:\MIS_DATABASE\Library\ALTIUM_TOOL\PCB_FOOTPRINTS\Altium_Footprint_Lib.PcbLib; Height: 1.10MM; Library Path: Y:\MIS_DATABASE\Library\ALTIUM_TOOL\SCHEMATICS_PARTS\MS_ANALOG-APPLICATION_Library.schlib; Mfr_name: TEXAS INSTRUMENTS; Mistral Part No: 140118090001-R; Package: VSSOP10; Part_type: ICS\ANALOG\SWITCH; Project: DLRL_DFP_ATRUC CARD; RoHS: RoHS; Temperature: -40°C+85°C; Tolerance: NA; Voltage: NA; Wattage: NA; Weight: NA; Datasheet: Y:\MIS_DATABASE\DATASHEETS\ICS\ANALOG\TMUX154EXXX.PDF
U46 = TXB0106RGYR_VQFN16: IC 6-BIT BIDIRECTIONAL VOLTAGE-LEVEL TRANSLATOR VQFN16; Chkd/date: MANIRAJA/010218; Crtd /date: MANIRAJA/010218; Custom_Duty: 15%; Customs_HS_Code: 85423100; Distributor_name: DIGIKEY; Distributor_part_number: 296-23868-1-ND; Height: 1.00MM; Mfr_name: TEXAS INSTRUMENTS; Mistral Part No: 141018020001-R; Package: VQFN16; Part_type: ICS\INTERFACE\LEVEL TRANSLATOR; Project: NPOL_SAR_ADC; RoHS: RoHS; Temperature: -40°C+85°C; Tolerance: NA; Voltage: NA; Wattage: NA; Weight: 37.2mg; Datasheet: Y:\MIS_DATABASE\DATASHEETS\ICS\INTERFACE\TXB0106X.PDF
C13 = CAP: CAP CERAMIC 1uF 16V 20% X5R 0201; Chkd/date: MANIRAJA/300520; Crtd /date: ALVY/260520; Custom_Duty: 15%; Customs_HS_Code: 85322990; Distributor_name: DIGIKEY; Distributor_part_number: 490-18654-1-ND; Footprint Path: Y:\MIS_DATABASE\Library\ALTIUM_TOOL\PCB_FOOTPRINTS\Altium_Footprint_Lib.PcbLib; Height: 0.39MM; Library Path: Y:\MIS_DATABASE\Library\ALTIUM_TOOL\SCHEMATICS_PARTS\MS_DISCRETE_Library.schlib; Mfr_name: MURATA; Mfr_part_number: GRM033R61C105ME15D; Mistral Part No: 120018090038-R; Package: 0201; Part_type: CAPACITORS\CERAMIC; Project: QCS610_NANOSOM; RoHS: RoHS; Temperature: -55°C+85°C; Tolerance: 20%; Voltage: 16V; Wattage: NA; Weight: 0.33mg; Datasheet: Y:\MIS_DATABASE\DATASHEETS\CAPACITORS\GRM033R61C105ME15.PDF
C71-C73 C75-C77 = CAP: CAP CERAMIC 1000pF 50V 5% C0G(NP0) 0402; Chkd/date: VASANTHA/281216; Crtd /date: MAZHAR/290806; Custom_Duty: 15%; Customs_HS_Code: 85322990; Distributor_name: DIGIKEY; Distributor_part_number: 490-3244-1-ND; Footprint Path: Y:\MIS_DATABASE\Library\ALTIUM_TOOL\PCB_FOOTPRINTS\Altium_Footprint_Lib.PcbLib; Height: 0.55MM; Library Path: Y:\MIS_DATABASE\Library\ALTIUM_TOOL\SCHEMATICS_PARTS\MS_DISCRETE_Library.schlib; Mfr_name: MURATA; Mfr_part_number: GRM1555C1H102JA01D; Mistral Part No: 120016110009-R; Package: 0402; Part_type: CAPACITORS\CERAMIC; Project: SVDO_RMB_MMA; RoHS: RoHS; Temperature: -55°C+125°C; Tolerance: 5%; Voltage: 50V; Wattage: NA; Weight: 6mg; Datasheet: Y:\MIS_DATABASE\DATASHEETS\CAPACITORS\MURATA-GXX-SER_NOV17.PDF
C267 = CAP: CAP CERAMIC 4700pF 50V 10% X7R 0402; Chkd/date: MANIRAJA/170820; Crtd /date: ALVY/170820; Custom_Duty: 15%; Customs_HS_Code: 85322990; Distributor_name: DIGIKEY; Distributor_part_number: 732-7560-1-ND; Footprint Path: Y:\MIS_DATABASE\Library\ALTIUM_TOOL\PCB_FOOTPRINTS\Altium_Footprint_Lib.PcbLib; Height: 0.55MM; Library Path: Y:\MIS_DATABASE\Library\ALTIUM_TOOL\SCHEMATICS_PARTS\MS_DISCRETE_Library.schlib; Mfr_name: WURTH ELECTRONICS; Mfr_part_number: 885012205065; Mistral Part No: 120009030440-R; Package: 0402; Part_type: CAPACITORS\CERAMIC; Project: AM64x_EVM_BRD; RoHS: RoHS; Temperature: -55°C+125°C; Tolerance: 10%; Voltage: 50V; Wattage: NA; Weight: 12mg; Datasheet: Y:\MIS_DATABASE\DATASHEETS\CAPACITORS\885012205065.PDF
J11 = HEADER_3X1: CON HDR 1X3 2.54MM PITCH ST TH; Chkd/date: VASANTHA/211015; Crtd /date: VASANTHA/211015; Custom_Duty: 24%; Customs_HS_Code: 85369090; Distributor_name: DIGIKEY; Distributor_part_number: 732-5316-ND; Height: 8.54MM; Mfr_name: WURTH ELECTRONICS INC; Mfr_part_number: 61300311121; Mistral Part No: 150015100037-R; Package: THRU-HOLE; Part_type: CONNECTOR\HEADERS; Project: CYPHY_ROADKILL; RoHS: RoHS; Temperature: NA; Tolerance: NA; Voltage: NA; Wattage: NA; Weight: NA; Datasheet: Y:\MIS_DATABASE\DATASHEETS\CONNECTORS\6130XXX.PDF
J12 J21 = HEADER_5X1: CON HDR 1X5 2.54MM PITCH ST TH; Chkd/date: MANIRAJA/121120; Crtd /date: ALVY/111120; Custom_Duty: 24%; Customs_HS_Code: 85369090; Distributor_name: DIGIKEY; Distributor_part_number: 732-5318-ND; Footprint Path: Y:\MIS_DATABASE\Library\ALTIUM_TOOL\PCB_FOOTPRINTS\Altium_Footprint_Lib.PcbLib; Height: 8.54MM; Library Path: Y:\MIS_DATABASE\Library\ALTIUM_TOOL\SCHEMATICS_PARTS\MS_CONNECTOR_Library.schlib; Mfr_name: WURTH ELEKTRONIK; Mfr_part_number: 61300511121; Mistral Part No: 150020110010-R; Package: THRU-HOLE; Part_type: CONNECTOR\HEADERS; Project: TI_AM243x LP EVM; RoHS: RoHS; Temperature: -40°C+105°C; Tolerance: NA; Voltage: NA; Wattage: NA; Weight: 280mg; Datasheet: Y:\MIS_DATABASE\DATASHEETS\CONNECTORS\6130XXX.PDF
J16 = HEADER_5X2: CON HDR 2X5 2.54MM PITCH ST TH; Chkd/date: MANIRAJA/121120; Crtd /date: ALVY/111120; Custom_Duty: 24%; Customs_HS_Code: 85369090; Distributor_name: DIGIKEY; Distributor_part_number: 732-2672-ND; Footprint Path: Y:\MIS_DATABASE\Library\ALTIUM_TOOL\PCB_FOOTPRINTS\Altium_Footprint_Lib.PcbLib; Height: 8.54MM; Library Path: Y:\MIS_DATABASE\Library\ALTIUM_TOOL\SCHEMATICS_PARTS\MS_CONNECTOR_Library.schlib; Mfr_name: WURTH ELEKTRONIK; Mfr_part_number: 61301021121; Mistral Part No: 150020110011-R; Package: THRU-HOLE; Part_type: CONNECTOR\HEADERS; Project: TI_AM243x LP EVM; RoHS: RoHS; Temperature: -40°C+105°C; Tolerance: NA; Voltage: NA; Wattage: NA; Weight: 550mg; Datasheet: Y:\MIS_DATABASE\DATASHEETS\CONNECTORS\6130XX21121.PDF
R272-R274 R279-R281 = RESISTOR: RES 49.9K 1/10W 1% 0402; Chkd/date: MANIRAJA/130617; Crtd /date: BAVISH/020611; Custom_Duty: 15%; Customs_HS_Code: 85332119; Distributor_name: DIGIKEY; Distributor_part_number: P49.9KLCT-ND; Footprint Path: Y:\MIS_DATABASE\Library\ALTIUM_TOOL\PCB_FOOTPRINTS\Altium_Footprint_Lib.PcbLib; Height: 0.40MM; Library Path: Y:\MIS_DATABASE\Library\ALTIUM_TOOL\SCHEMATICS_PARTS\MS_DISCRETE_Library.schlib; Mfr_name: PANASONIC-ECG; Mfr_part_number: ERJ-2RKF4992X; Mistral Part No: 110011060018-R; Package: 0402; Part_type: RESISTORS\FIXED; Project: AM4515_EVM_LCD; RoHS: RoHS; Temperature: -55°C+155°C; Tolerance: 1%; Voltage: NA; Wattage: 1/10W; Weight: 0.8mg; Datasheet: Y:\MIS_DATABASE\DATASHEETS\RESISTORS\PAN-ERJSER_NOV17.PDF
R277 R278 = RESISTOR: RES 59E 1/16W 1% 0402; Chkd/date: ALVY/091220; Crtd /date: MANIRAJA/091220; Custom_Duty: 15%; Customs_HS_Code: 85332119; Distributor_name: DIGIKEY; Distributor_part_number: YAG3194CT-ND; Footprint Path: Y:\MIS_DATABASE\Library\ALTIUM_TOOL\PCB_FOOTPRINTS\Altium_Footprint_Lib.PcbLib; Height: 0.40MM; Library Path: Y:\MIS_DATABASE\Library\ALTIUM_TOOL\SCHEMATICS_PARTS\MS_DISCRETE_Library.schlib; Mfr_name: YAGEO AMERICA; Mfr_part_number: RC0402FR-0759RL; Mistral Part No: 110020120010-R; Package: 0402; Part_type: RESISTORS\FIXED; Project: TI_AM243x LP EVM; RoHS: RoHS; Temperature: -55°C+155°C; Tolerance: 1%; Voltage: NA; Wattage: 1/16W; Weight: 0.65mg; Datasheet: Y:\MIS_DATABASE\DATASHEETS\RESISTORS\RCXXXXL-SER_MAR18.PDF
U3 = OSC4_EQXP-HC33: OSC 25.000MHz 3.3V CMOS SMD; Chkd/date: MANIRAJA/070121; Crtd /date: ALVY/060121; Custom_Duty: 24%; Customs_HS_Code: 85437099; Distributor_name: NA; Distributor_part_number: NA; Footprint Path: Y:\MIS_DATABASE\Library\ALTIUM_TOOL\PCB_FOOTPRINTS\Altium_Footprint_Lib.PcbLib; Height: 1.20MM; Library Path: Y:\MIS_DATABASE\Library\ALTIUM_TOOL\SCHEMATICS_PARTS\MS_DISCRETE_Library.schlib; Mfr_name: WURTH ELEKTRONIK; Mfr_part_number: 831055678; Mistral Part No: 130021010008-R; Package: SMD; Part_type: OSCILLATORS; Project: TI_AM243x LP EVM; RoHS: RoHS; Temperature: -40°C+85°C; Tolerance: NA; Voltage: 3.3V; Wattage: NA; Weight: NA; Datasheet: Y:\MIS_DATABASE\DATASHEETS\MISC\CRY_OSC\831055678.PDF
U6 = LMK1C1103_TSSOP8: IC 3-CHANNEL LVCMOS CLOCK BUFFER TSSOP8; Chkd/date: MANIRAJA/080920; Crtd /date: ALVY/070920; Custom_Duty: 15%; Customs_HS_Code: 85423100; Distributor_name: DIGIKEY; Distributor_part_number: 296-LMK1C1103PWRCT-ND; Footprint Path: Y:\MIS_DATABASE\Library\ALTIUM_TOOL\PCB_FOOTPRINTS\Altium_Footprint_Lib.PcbLib; Height: 1.20MM; Library Path: Y:\MIS_DATABASE\Library\ALTIUM_TOOL\SCHEMATICS_PARTS\MS_COMBINATIONAL_Library.schlib; Mfr_name: TEXAS INSTRUMENTS; Mistral Part No: 141020090002-R; Package: TSSOP8; Part_type: ICS\DIGITAL\COMBINATIONAL; Project: AM64X_SKEVM; RoHS: RoHS; Temperature: -40°C+125°C; Tolerance: NA; Voltage: NA; Wattage: NA; Weight: 34.1mg; Datasheet: Y:\MIS_DATABASE\DATASHEETS\ICS\DIGITAL\COMBINATIONAL\LMK1C110X.PDF
U44 = TCAN1044V-Q1_SON8: IC AUTO FAULT-PROTECTED CAN FD TRANSCEIVER SON8; Chkd/date: MANIRAJA/241220; Crtd /date: ALVY/231220; Custom_Duty: 15%; Customs_HS_Code: 85423100; Distributor_name: DIGIKEY; Distributor_part_number: 296-TCAN1044VDRBRQ1CT-ND; Footprint Path: Y:\MIS_DATABASE\Library\ALTIUM_TOOL\PCB_FOOTPRINTS\Altium_Footprint_Lib.PcbLib; Height: 1.00MM; Library Path: Y:\MIS_DATABASE\Library\ALTIUM_TOOL\SCHEMATICS_PARTS\MS_TELECOM_Library.schlib; Mfr_name: TEXAS INSTRUMENTS; Mistral Part No: 143020120003-R; Package: SON8; Part_type: ICS\TELECOM\TRANSCEIVER; Project: TI_AM243x LP EVM; RoHS: RoHS; Temperature: -40°C+125°C; Tolerance: NA; Voltage: NA; Wattage: NA; Weight: NA; Datasheet: Y:\MIS_DATABASE\DATASHEETS\ICS\TELECOM\TCAN1044-Q1.PDF
C10 = CAP: CAP CERAMIC 4.7uF 10V 20% X5R 0402; Chkd/date: MANIRAJA/110718; Crtd /date: ALVY/110718; Custom_Duty: 15%; Customs_HS_Code: 85322990; Distributor_name: DIGIKEY; Distributor_part_number: 490-14306-1-ND; Footprint Path: Y:\MIS_DATABASE\Library\ALTIUM_TOOL\PCB_FOOTPRINTS\Altium_Footprint_Lib.PcbLib; Height: 0.65MM; Library Path: Y:\MIS_DATABASE\Library\ALTIUM_TOOL\SCHEMATICS_PARTS\MS_DISCRETE_Library.schlib; Mfr_name: MURATA; Mfr_part_number: GRM155R61A475MEAAD; Mistral Part No: 120012060002-R; Package: 0402; Part_type: CAPACITORS\CERAMIC; Project: TI_J7SVB_PCIE_ADD-ON-CARD; RoHS: RoHS; Temperature: -55°C+85°C; Tolerance: 20%; Voltage: 10V; Wattage: NA; Weight: 14mg; Datasheet: Y:\MIS_DATABASE\DATASHEETS\CAPACITORS\GRM155R61A475MEAAD.PDF
R54 = RESISTOR: RES 100K 1/16W 1% 0402; Chkd/date: MANIRAJA/110917; Crtd /date: MANIRAJA/110917; Custom_Duty: 15%; Customs_HS_Code: 85332119; Distributor_name: DIGIKEY; Distributor_part_number: 311-100KLRCT-ND; Footprint Path: Y:\MIS_DATABASE\Library\ALTIUM_TOOL\PCB_FOOTPRINTS\Altium_Footprint_Lib.PcbLib; Height: 0.40MM; Library Path: Y:\MIS_DATABASE\Library\ALTIUM_TOOL\SCHEMATICS_PARTS\MS_DISCRETE_Library.schlib; Mfr_name: YAGEO AMERICA; Mfr_part_number: RC0402FR-07100KL; Mistral Part No: 110014060043-R; Package: 0402; Part_type: RESISTORS\FIXED; Project: CRADE RF CARD; RoHS: RoHS; Temperature: -55°C+155°C; Tolerance: 1%; Voltage: NA; Wattage: 1/16W; Weight: 0.65mg; Datasheet: Y:\MIS_DATABASE\DATASHEETS\RESISTORS\RCXXXXL-SER_MAR18.PDF
U2 = S25HL512TFAMHI01_SOIC16: IC 3V 512MB QUAD SPI SEMPER FLASH MEMORY SOIC16; Chkd/date: MANIRAJA/231120; Crtd /date: ALVY/201120; Custom_Duty: 15%; Customs_HS_Code: 85423100; Distributor_name: DIGIKEY; Distributor_part_number: 428-S25HL512TFAMHI010-ND; Footprint Path: Y:\MIS_DATABASE\Library\ALTIUM_TOOL\PCB_FOOTPRINTS\Altium_Footprint_Lib.PcbLib; Height: 2.65MM; Library Path: Y:\MIS_DATABASE\Library\ALTIUM_TOOL\SCHEMATICS_PARTS\MS_MISCMEMORY_Library.schlib; Mfr_name: CYPRESS; Mistral Part No: 141120110006-R; Package: SOIC16; Part_type: ICS\DIGITAL\MEMORY; Project: TI_AM243x LP EVM; RoHS: RoHS; Temperature: -40°C+85°C; Tolerance: NA; Voltage: NA; Wattage: NA; Weight: NA; Datasheet: Y:\MIS_DATABASE\DATASHEETS\ICS\MEMORY\S25HXXXXT.PDF
U17 = AT24HC04B-TH-B_TSSOP8: IC 1MBIT I2C SERIAL EEPROM TSSOP8; Chkd/date: NAVEED/241114; Crtd /date: VASANTHA/230914; Custom_Duty: 15%; Customs_HS_Code: 85423100; Distributor_name: DIGIKEY; Distributor_part_number: AT24CM01-XHD-TCT-ND; Height: 1.20MM; Mfr_name: ATMEL; Mfr_part_number: AT24CM01-XHD-T; Mistral Part No: 141114090006-R; Package: TSSOP8; Part_type: ICS\DIGITAL\MEMORY; Project: GALILEO_EVM; RoHS: RoHS; Temperature: -40°C+85°C; Tolerance: NA; Voltage: NA; Wattage: NA; Weight: 158mg; Datasheet: Y:\MIS_DATABASE\DATASHEETS\ICS\MEMORY\AT24CM01.PDF
U31 = SN74LVC1G08DBVRE4_SOT23-5: IC SINGLE 2-INPUT POSITIVE AND GATE SOT23-5; Automotive Alternate_mfr_name: TEXAS INSTRUMENTS; Automotive Alternate_mfr_part_number: SN74LVC1G08QDBVRQ1; Chkd/date: SUHAS/221010; Crtd /date: USMAN/151008; Custom_Duty: 15%; Customs_HS_Code: 85423100; Distributor_name: DIGIKEY; Distributor_part_number: SN74LVC1G08DBVRE4-ND; Height: 1.45MM; Mfr_name: TEXAS INSTRUMENTS; Mistral Part No: 141009060026-R; Part_type: ICS\DIGITAL\GATES; Project: KHAN_MAIN; RoHS: Sb/ Br FREE; Temperature: -40°C+85°C; Datasheet: Y:\MIS_DATABASE\DATASHEETS\ICS\DIGITAL\GATES\SN74LVC1G08.PDF
U18 = AM243X_SOC_LP_EVM_BGA293: IC AM243x SoC_LP_EVM MICROPROCESSOR BGA293; Chkd/date: MANIRAJA/131120; Crtd /date: ALVY/121120; Custom_Duty: 15%; Customs_HS_Code: 85423100; Distributor_name: NA; Distributor_part_number: NA; Footprint Path: Y:\MIS_DATABASE\Library\ALTIUM_TOOL\PCB_FOOTPRINTS\Altium_Footprint_Lib.PcbLib; Height: 1.00MM; Library Path: Y:\MIS_DATABASE\Library\ALTIUM_TOOL\SCHEMATICS_PARTS\MS_MICROPROCESSOR_Library.schlib; Library Ref: AM243x SoC_LP_EVM_BGA293; Mfr_name: TEXAS INSTRUMENTS; Mistral Part No: 141220110003; Package: BGA293; Part_type: ICS\DIGITAL\MICROPROCESSOR; Project: TI_AM243x LP EVM; RoHS: NA; Temperature: NA; Tolerance: NA; Voltage: NA; Wattage: NA; Weight: NA; Datasheet: Y:\MIS_DATABASE\DATASHEETS\ICS\DIGITAL\MICROCONTROLLER\AM243x SoC-FP.PDF

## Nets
DGND: C3.1 C9.1 C10.2 C12.2 C13.2 C16.1 C24.2 C30.1 C41.2 C44.2 C45.2 C59.2 C60.2 C71.2 C72.2 C73.2 C74.2 C75.2 C76.2 C77.2 C90.2 C94.2 C257.2 C259.2 C260.2 C265.1 C267.2 C269.2 C270.2 J11.2 J12.5 J16.3 J16.4 J17.1 J21.5 R49.1 R54.2 R78.1 R87.1 R120.1 R121.1 R122.1 R126.1 R128.1 R190.1 R234.1 R276.1 U2.10(VSS) U3.2(GND) U6.4(GND) U8.1(~{1OE}) U8.4(~{2OE}) U8.7(GND) U8.10(~{3OE}) U8.13(~{4OE}) U11.3(GND) U16.2(GND) U17.4(GND) U22.5(GND) U22.9(~{EN}) U25.2(1DIR) U25.3(2DIR) U25.8(GND1) U25.9(GND2) U25.14(~{2OE}) U25.15(~{1OE}) U30.5(GND) U30.9(~{EN}) U31.3(GND) U42.3(A2) U42.4(~{OE}) U42.5(GND) U42.6(B2) U44.2(GND) U44.9(EP) U46.9(GND) U46.17(EP) ; also on sheet 10 11 16 17 18 19 20 21 22 23 24 25 26 27 28
VCC3V3_XDS: C44.1 C60.1 C260.1 U16.7(VCCB) U25.16(VCCB) U42.8(VCCB) ; also on sheet 22
VCC_5V0_CAN: C257.1 R270.2 TP50.1(TP) U44.3(VCC)
VDD_1V8: C30.2 U11.5(VCC) ; also on sheet 10 25 28
CPSW_RGMII1_TD0: U18.Y14(PRG1_PRU1_GPO7) ; also on sheet 16
CPSW_RGMII1_TD1: U18.Y16(PRG1_PRU1_GPO9) ; also on sheet 16
CPSW_RGMII1_TD2: U18.U13(PRG1_PRU1_GPO10) ; also on sheet 16
CPSW_RGMII1_TD3: U18.AA14(PRG1_PRU1_GPO17) ; also on sheet 16
CPSW_RGMII1_TX_CTL: U18.W16(PRG1_PRU0_GPO9) ; also on sheet 16
CPSW_RGMII1_TXC: R287.2 ; also on sheet 16
EEPROM_A1: R121.2 U17.2(A1)
EEPROM_A2: R122.2 U17.3(A2)
EEPROM_WP: R89.1 U17.7(WP)
EHRPWM2_A: U30.3(A1) ; also on sheet 19
EHRPWM2_B: U30.7(B1) ; also on sheet 19
eQEP1_A: C77.1 J12.1 R279.2 U46.16(B1)
eQEP1_A_LS: U46.1(A1) ; also on sheet 11
eQEP1_B: C76.1 J12.2 R280.2 U46.14(B2)
eQEP1_B_LS: U46.3(A2) ; also on sheet 11
eQEP1_I: C75.1 J12.3 R281.2 U46.13(B3)
eQEP1_I_LS: U46.4(A3) ; also on sheet 11
eQEP2_A: C73.1 J21.1 R272.2 U46.12(B4)
eQEP2_A_LS: U46.5(A4) ; also on sheet 11
eQEP2_B: C72.1 J21.2 R273.2 U46.11(B5)
eQEP2_B_LS: U46.6(A5) ; also on sheet 11
eQEP2_I: C71.1 J21.3 R274.2 U46.10(B6)
eQEP2_I_LS: U22.3(A1) U46.7(A6)
FSI/BP_MUX_SEL: R190.2 U30.1(SEL) ; also on sheet 11
FSI_RX0_CLK: J16.1 U30.2(A0)
FSI_RX0_D0: J16.5 U30.8(B0)
FSI_RX0_D1: J16.7 ; also on sheet 11
FSI_RX0CLK_PWM2A: U30.4(A) ; also on sheet 11
FSI_RX0D0_PWM2B: U30.6(B) ; also on sheet 11
FSI_TX0_CLK: J16.2 ; also on sheet 11
FSI_TX0_D0: J16.6 ; also on sheet 11
FSI_TX0_D1: J16.8 ; also on sheet 11
GPIO1_61: TP34.1(TP) U22.7(B1)
GPIO_OSPI0_RESET_N: R181.1 U18.M20(OSPI0_CSN1) U31.1(A)
GPIO_RGMII2_PHY_RSTn: U18.Y15(PRG1_PRU1_GPO18) ; also on sheet 18
LMK_1G: R32.1 U6.2(1G)
LMK_CLK_IN: R26.2 U6.1(CLKIN)
LMK_CLK_IN_R: R26.1 U3.3(OUTPUT)
MCAN0_H: J11.1 R278.1 U44.7(CANH)
MCAN0_L: J11.3 R277.2 U44.6(CANL)
MCAN0_RX: R263.2 U44.4(RXD)
MCAN0_RX_MUX: U22.6(B) ; also on sheet 11
MCAN0_RX_SYNC3_OUT: R131.1 R263.1 U22.8(B0)
MCAN0_STB: R276.2 U44.8(STB) ; also on sheet 11
MCAN0_T: C267.1 R277.1 R278.2
MCAN0_TX: R259.2 U44.1(TXD)
MCAN0_TX_eQEP2_I: U22.4(A) ; also on sheet 11
MCAN0_TX_SYNC2_OUT: R140.1 R259.1 U22.2(A0)
MCAN/eQEP_MUX_SEL: R128.2 U22.1(SEL) ; also on sheet 11
MCU_PORz: U18.C20(MCU_PORZ) ; also on sheet 10
MCU_RESETSTATz: R126.2 R180.1 TP31.1(TP) U18.A6(MCU_RESETSTATZ)
MCU_RESETz: U18.A5(MCU_RESETZ) ; also on sheet 10
MCU_SAFTY_ERRz: TP22.1(TP) U18.B20(MCU_SAFETY_ERRORN)
MCU_UART0_CTS#: U8.11(4B) U18.D4(MCU_UART0_CTSN)
MCU_UART0_RTS#: U8.5(2A) U18.C2(MCU_UART0_RTSN)
MCU_UART0_RXD: U8.8(3B) U18.D6(MCU_UART0_RXD)
MCU_UART0_TXD: U8.2(1A) U18.B2(MCU_UART0_TXD)
OSC0_XO: R78.2 U18.C21(MCU_OSC0_XO)
OSC_STB#: R49.2 U3.1(ENABLE/DISABLE)
OSPI0_CLK: R54.1 R63.2 U2.16(CK)
OSPI0_CLK_R: R63.1 U18.P20(OSPI0_CLK)
OSPI0_CS0_N: R183.1 U2.7(CS#) U18.L20(OSPI0_CSN0)
OSPI0_D0: R36.1 U2.15(DQ0/SI) U18.L19(OSPI0_D0)
OSPI0_D1: R10.1 U2.8(DQ1/SO) U18.N20(OSPI0_D1)
OSPI0_D2: R5.1 U2.9(DQ2/WP#) U18.L21(OSPI0_D2)
OSPI0_D3: R37.1 U2.1(DQ3/RESET#) U18.N19(OSPI0_D3)
OSPI0_DQS: R213.1 U18.P17(OSPI0_DQS)
OSPI0_DQS_R: R65.1 R213.2
OSPI0_LBCLKO: R65.2 U18.M21(OSPI0_LBCLKO)
PORZ_OUT: R87.2 R179.1 TP14.1(TP) U18.D18(PORZ_OUT) ; also on sheet 11 17 18 21
PRG1_CPSW_ETH1_LED_1000/RX_ER: U18.U14(PRG1_PRU0_GPO5) ; also on sheet 17
PRG1_CPSW_ETH1_LED_LINK: U18.Y13(PRG1_PRU0_GPO8) ; also on sheet 17
PRG1_CPSW_ETH2_LED_1000/RX_ER: U18.AA11(PRG1_PRU1_GPO5) ; also on sheet 18
PRG1_CPSW_ETH2_LED_LINK: U18.W11(PRG1_PRU1_GPO8) ; also on sheet 18
PRG1_CPSW_RGMII1_CLK: R25.2 ; also on sheet 17
PRG1_CPSW_RGMII1_CLK_R: R25.1 U6.8(Y1)
PRG1_CPSW_RGMII2_CLK: R50.2 ; also on sheet 18
PRG1_CPSW_RGMII2_CLK_R: R50.1 U6.5(Y2)
PRG1_CPSW_RGMII2_RD0: U18.AA10(PRG1_PRU1_GPO0) ; also on sheet 18
PRG1_CPSW_RGMII2_RD1: U18.Y10(PRG1_PRU1_GPO1) ; also on sheet 18
PRG1_CPSW_RGMII2_RD2: U18.Y11(PRG1_PRU1_GPO2) ; also on sheet 18
PRG1_CPSW_RGMII2_RD3: U18.V12(PRG1_PRU1_GPO3) ; also on sheet 18
PRG1_CPSW_RGMII2_RX_CTL: U18.Y12(PRG1_PRU1_GPO4) ; also on sheet 18
PRG1_CPSW_RGMII2_RXC: U18.V10(PRG1_PRU1_GPO6) ; also on sheet 18
PRG1_CPSW_RGMII2_TD0: U18.Y6(PRG1_PRU1_GPO11) ; also on sheet 18
PRG1_CPSW_RGMII2_TD1: U18.AA8(PRG1_PRU1_GPO12) ; also on sheet 18
PRG1_CPSW_RGMII2_TD2: U18.Y9(PRG1_PRU1_GPO13) ; also on sheet 18
PRG1_CPSW_RGMII2_TD3: U18.W9(PRG1_PRU1_GPO14) ; also on sheet 18
PRG1_CPSW_RGMII2_TX_CTL: U18.V9(PRG1_PRU1_GPO15) ; also on sheet 18
PRG1_CPSW_RGMII2_TXC: U18.Y8(PRG1_PRU1_GPO16) ; also on sheet 18
PRG1_CPSW_RGMII_INTn: U18.AA13(PRG1_PRU1_GPO19) ; also on sheet 17 18
PRG1_IEP0_EDC_LATCH_IN0: U18.Y4(PRG1_PRU0_GPO18) ; also on sheet 19
PRG1_IEP0_EDC_LATCH_IN1: U18.V13(PRG1_PRU0_GPO7) ; also on sheet 19
PRG1_IEP0_EDC_SYNC_OUT0: U18.U3(PRG1_PRU0_GPO19) ; also on sheet 19
PRG1_IEP0_EDC_SYNC_OUT1: U18.T2(PRG1_PRU0_GPO17) ; also on sheet 19
PRG1_MDIO0_MDC: U18.W1(PRG1_MDIO0_MDC) ; also on sheet 17 18
PRG1_MDIO0_MDIO: U18.V2(PRG1_MDIO0_MDIO) ; also on sheet 17 18
PRG1_RGMII1_RD0: U18.V4(PRG1_PRU0_GPO0) ; also on sheet 16
PRG1_RGMII1_RD1: U18.W5(PRG1_PRU0_GPO1) ; also on sheet 16
PRG1_RGMII1_RD2: U18.AA4(PRG1_PRU0_GPO2) ; also on sheet 16
PRG1_RGMII1_RD3: U18.Y5(PRG1_PRU0_GPO3) ; also on sheet 16
PRG1_RGMII1_RX_CTL: U18.AA5(PRG1_PRU0_GPO4) ; also on sheet 16
PRG1_RGMII1_RXC: U18.Y2(PRG1_PRU0_GPO6) ; also on sheet 16
PRG1_RGMII1_TD0: U18.V5(PRG1_PRU0_GPO11) ; also on sheet 16
PRG1_RGMII1_TD1: U18.W2(PRG1_PRU0_GPO12) ; also on sheet 16
PRG1_RGMII1_TD2: U18.V6(PRG1_PRU0_GPO13) ; also on sheet 16
PRG1_RGMII1_TD3: U18.AA7(PRG1_PRU0_GPO14) ; also on sheet 16
PRG1_RGMII1_TX_CTL: U18.Y7(PRG1_PRU0_GPO15) ; also on sheet 16
PRG1_RGMII1_TXC: R286.2 ; also on sheet 16
QSPI_RST_N: U2.3(RESET#) U31.4(Y)
SOC_CLKIN: U11.4(Y) U18.D20(MCU_OSC0_XI)
SOC_CLKIN_BUFF: R46.2 U11.2(A)
SOC_CLKIN_BUFF_R: R46.1 U6.3(Y0)
SOC_CPSW_RGMII1_TXC: R287.1 U18.W13(PRG1_PRU0_GPO10)
SOC_EMU0: U16.5(A1) U18.C5(EMU0)
SOC_EMU1: U16.4(A2) U18.B3(EMU1)
SoC_I2C0_SCL: U17.6(SCL) ; also on sheet 11 19 23
SoC_I2C0_SDA: U17.5(SDA) ; also on sheet 11 19 23
SOC_PRG1_RGMII1_TXC: R286.1 U18.W6(PRG1_PRU0_GPO16)
SoC_RESET_REQz: U18.C17(RESET_REQZ) ; also on sheet 10
SOC_RESETSTATz: R234.2 TP13.1(TP) U18.E19(RESETSTATZ)
SOC_TCK: R162.1 U18.C6(TCK)
SOC_TDI: U18.A3(TDI) U25.5(1A2)
SOC_TDO: R271.1 U42.2(A1)
SOC_TMS: U18.B4(TMS) U25.6(2A1)
SOC_TRST#: R120.2 U18.B6(TRSTN) U25.7(2A2)
SYNC2_OUT: R140.2 ; also on sheet 19
SYNC3_OUT: R131.2 ; also on sheet 19
UART0_HDR_CTS#: J17.2 U8.6(2B)
UART0_HDR_RTS#: J17.6 U8.12(4A)
UART0_HDR_RXD: J17.5 U8.3(1B)
UART0_HDR_TXD: J17.4 U8.9(3A)
VSYS_3V3: C3.2 C9.2 C10.1 C12.1 C13.1 C16.2 C24.1 C41.1 C45.1 C59.1 C74.1 C90.1 C94.1 C259.1 C265.2 C270.1 J16.10 R5.2 R10.2 R32.2 R36.2 R37.2 R89.2 R181.2 R183.2 U2.2(VCC) U3.4(VDD) U6.6(VDD) U8.14(VCC) U16.3(VCCA) U16.6(OE) U17.8(VCC) U22.10(VCC) U25.1(VCCA) U30.10(VCC) U31.5(VCC) U42.1(VCCA) U44.5(NC/VIO) U46.2(VCCA) U46.8(OE) ; also on sheet 10 11 16 17 18 19 20 21 22 23 24 25 27 28
VSYS_5V0: C269.1 J12.4 J21.4 R270.1 R272.1 R273.1 R274.1 R279.1 R280.1 R281.1 U46.15(VCCB) ; also on sheet 10 19 20 25 26 27 28
XDS110_EMU0: U16.8(B1) ; also on sheet 22
XDS110_EMU1: U16.1(B2) ; also on sheet 22
XDS110_TCK: U25.13(1B1) ; also on sheet 22
XDS110_TDI: U25.12(1B2) ; also on sheet 22
XDS110_TDO: U42.7(B1) ; also on sheet 22
XDS110_TMS: U25.11(2B1) ; also on sheet 22
XDS110_TRST#: U25.10(2B2) ; also on sheet 22
N30174920: R179.2 R180.2 U31.2(B)
N30625746: R271.2 U18.B5(TDO)
N30979572: R162.2 U25.4(1A1)

Not connected (* = marked no-connect by the designer): J16 9*; J17 3*; U2 4(DNU1)* 5(DNU2)* 6(DNU3)* 11(DNU4)* 12(DNU5)* 13(DNU6)* 14(DNU7)*; U6 7(NC)*; U11 1(NC)*; U17 1(NC)*; U18 J13(RSVD)*

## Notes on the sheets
sheet 12
- MCU UART0 Buffer & Header
- SoC_Connections
- Header_Connections
- MCU_UART0_TXD
- UART0_HDR_RXD - Pin5
- SoC Blocks
- MCU_UART0_RXD
- UART0_HDR_TXD - Pin4
- MCU_UART0_RTS#
- UART0_HDR_CTS# - Pin2
- MCU_UART0_CTS#
- UART0_HDR_RTS# - Pin6
- SoC Clock Buffer
- XDS110 JTAG Isolation Buffer
- GPIO0_50
- GPIO0_53
- GPIO0_62
- GPIO0_63
- GPIO0_64
- GPIO0_70
- GPIO0_73
- GPIO0_20
- GPIO0_84
sheet 13
- MCAN/eQEP FET Switch
- eQEP Level Shifter
- (To MCAN Transciever)
- (To eQEP level shifter)
- (From SoC GPIO)
- (To eQEP Headers)
- SEL = 0   A,B-->A0,B0
  SEL = 1   A,B-->A1,B1
- (By Default channel 0 (A0) is selected)
- FSI/BP FET Switch
- (To BP Header)
- (To BP Header)
- (From SoC GPIO)
- SEL = 0   A,B-->A0,B0
  SEL = 1   A,B-->A1,B1
- (By Default channel 0 (A0,B0) is selected)
sheet 14
- MCAN Transceiver & Header
- eQEP Headers
- 120E
- (From SoC GPIO)
- FSI Header
- SoC and Ethernet PHY Clock Buffer
- OE / ST#  Should be floating
  to enable the Oscilator
sheet 15
- QSPI FLASH
- GPIO0_12
- (MCU Warm Reset Output)
- (PORz Output)
- Board ID EEPROM
- I2C ADDRESS SET TO 0x50
